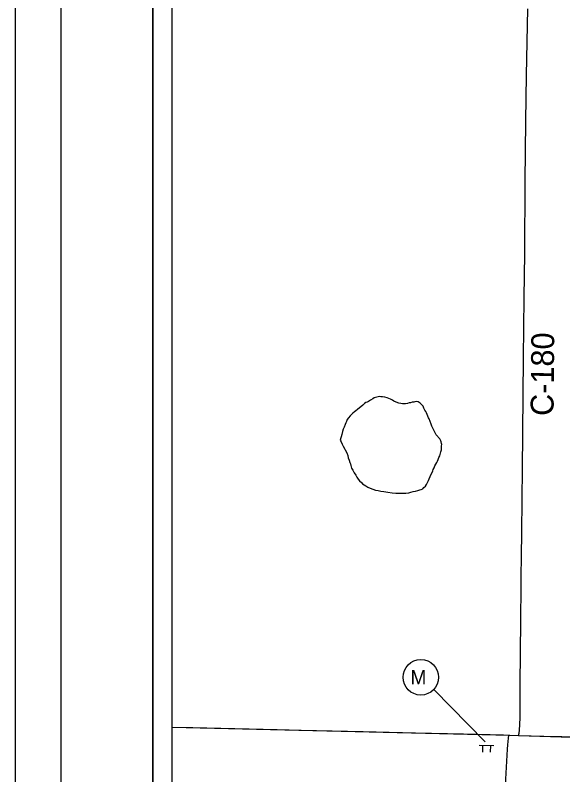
# Model space of a CAD drawing. Extents: x 1 to 1971, y -2 to 1107.
# Drawn here: x 1651.46 to 1657.44, y 1091.98 to 1100.26 of the extents above; entities that cross this region are included whole.
import ezdxf

# ---------------------------------------------------------------- set-up
doc = ezdxf.new("R2010")
doc.units = 0
for name, color, linetype in [('GM_X_County_Road', 7, 'Continuous'), ('GM_X_County_Road_Text', 7, 'Continuous'), ('GM_X_Minor_River', 7, 'Continuous'), ('GM_X_Township', 7, 'Continuous'), ('GM_X_Township_Road', 7, 'Continuous'), ('SH_Border', 7, 'Continuous'), ('SH_Cut_Line', 7, 'Continuous'), ('SH_Data', 7, 'Continuous'), ('SH_Text', 7, 'Continuous'), ('SN_P_Signs', 7, 'Continuous')]:
    doc.layers.add(name, color=color, linetype=linetype)

msp = doc.modelspace()

# ---------------------------------------------------------------- linework, layer by layer
at = {"layer": 'GM_X_County_Road'}
for points in [[(1656.9539, 1092.4077), (1656.9591, 1092.4332), (1656.9636, 1092.4628), (1656.965, 1092.4774), (1656.9669, 1092.5129), (1656.97, 1092.6154), (1656.9719, 1092.9605), (1656.9793, 1093.661), (1656.9822, 1094.0329), (1656.9825, 1094.1201), (1656.9871, 1094.3825), (1656.9878, 1094.6012), (1656.9921, 1094.995), (1656.9954, 1095.3015), (1657.0088, 1096.5272), (1657.0119, 1096.8554), (1657.0164, 1097.1823), (1657.0216, 1097.6632), (1657.0277, 1098.4513), (1657.0348, 1099.1076), (1657.0408, 1099.6108), (1657.0533, 1100.333)], [(1656.9539, 1092.4077), (1656.9591, 1092.4332), (1656.9636, 1092.4628), (1656.965, 1092.4774), (1656.9669, 1092.5129), (1656.97, 1092.6154), (1656.9719, 1092.9605), (1656.9793, 1093.661), (1656.9822, 1094.0329), (1656.9825, 1094.1201), (1656.9871, 1094.3825), (1656.9878, 1094.6012), (1656.9921, 1094.995), (1656.9954, 1095.3015), (1657.0088, 1096.5272), (1657.0119, 1096.8554), (1657.0164, 1097.1823), (1657.0216, 1097.6632), (1657.0277, 1098.4513), (1657.0348, 1099.1076), (1657.0408, 1099.6108), (1657.0533, 1100.333)], [(1656.6538, 1088.9713), (1656.6824, 1089.549), (1656.7502, 1090.7723), (1656.779, 1091.2527), (1656.8004, 1091.6678), (1656.8346, 1092.2577), (1656.8383, 1092.3049), (1656.8451, 1092.3768), (1656.8483, 1092.4109)], [(1656.6538, 1088.9713), (1656.6824, 1089.549), (1656.7502, 1090.7723), (1656.779, 1091.2527), (1656.8004, 1091.6678), (1656.8346, 1092.2577), (1656.8383, 1092.3049), (1656.8451, 1092.3768), (1656.8483, 1092.4109)], [(1656.8483, 1092.4109), (1656.9539, 1092.4077)], [(1656.8483, 1092.4109), (1656.9539, 1092.4077)]]:
    msp.add_lwpolyline(points, dxfattribs=at)
at = {"layer": 'GM_X_Minor_River'}
for points in [[(1656.055, 1095.6861), (1656.0243, 1095.7442), (1656.0138, 1095.7658), (1656.0086, 1095.7792), (1656.0008, 1095.8034), (1655.9774, 1095.86), (1655.9722, 1095.8735), (1655.9643, 1095.8896), (1655.9565, 1095.9085), (1655.9486, 1095.9247), (1655.9408, 1095.9408), (1655.9329, 1095.957), (1655.9224, 1095.9759), (1655.912, 1095.9975), (1655.8934, 1096.0165), (1655.8802, 1096.0327), (1655.8589, 1096.0464), (1655.8401, 1096.0493), (1655.824, 1096.0468), (1655.8105, 1096.0443), (1655.7944, 1096.0419), (1655.7755, 1096.0367), (1655.7593, 1096.0343), (1655.7432, 1096.0291), (1655.7216, 1096.0241), (1655.7001, 1096.0243), (1655.6867, 1096.0245), (1655.668, 1096.0274), (1655.6465, 1096.0331), (1655.6198, 1096.0415), (1655.5931, 1096.0552), (1655.5798, 1096.0634), (1655.5558, 1096.0771), (1655.5397, 1096.0827), (1655.5211, 1096.091), (1655.4943, 1096.0967), (1655.4701, 1096.0997), (1655.4514, 1096.1026), (1655.4379, 1096.1028), (1655.3922, 1096.0953), (1655.3787, 1096.0902), (1655.3625, 1096.0797), (1655.3381, 1096.0639), (1655.3164, 1096.0508), (1655.3029, 1096.0429), (1655.2894, 1096.0377), (1655.2732, 1096.0272), (1655.2569, 1096.0114), (1655.2324, 1095.9903), (1655.2189, 1095.9797), (1655.1972, 1095.964), (1655.1782, 1095.9481), (1655.1646, 1095.9376), (1655.1456, 1095.9218), (1655.1266, 1095.9059), (1655.1157, 1095.8927), (1655.0993, 1095.8715), (1655.0857, 1095.8529), (1655.0774, 1095.8316), (1655.0691, 1095.8156), (1655.0635, 1095.7996), (1655.0524, 1095.7703), (1655.0414, 1095.749), (1655.033, 1095.7224), (1655.0255, 1095.6907)], [(1655.0255, 1095.6907), (1655.0073, 1095.6283), (1655.018, 1095.6095), (1655.0286, 1095.5854), (1655.042, 1095.564), (1655.0819, 1095.489), (1655.0899, 1095.4622), (1655.0952, 1095.4354), (1655.1058, 1095.4086), (1655.1138, 1095.3845), (1655.1191, 1095.3711), (1655.1244, 1095.3524), (1655.1324, 1095.3229), (1655.1457, 1095.3015), (1655.1617, 1095.272), (1655.1777, 1095.2452), (1655.191, 1095.2237), (1655.2044, 1095.2023), (1655.2177, 1095.1862), (1655.2391, 1095.1647), (1655.2524, 1095.1513), (1655.2711, 1095.1405), (1655.2871, 1095.1298), (1655.3112, 1095.1163), (1655.3353, 1095.1029), (1655.3647, 1095.0921), (1655.3941, 1095.084), (1655.4208, 1095.0785), (1655.4502, 1095.0731), (1655.485, 1095.0676), (1655.5278, 1095.0595), (1655.5759, 1095.054), (1655.6134, 1095.0512), (1655.6455, 1095.0484), (1655.6696, 1095.0483), (1655.7017, 1095.0509), (1655.7258, 1095.0508), (1655.7552, 1095.0534), (1655.7793, 1095.0613), (1655.8034, 1095.0666), (1655.8302, 1095.0719), (1655.8543, 1095.0798), (1655.8757, 1095.0851), (1655.8918, 1095.0904), (1655.9079, 1095.0984), (1655.9213, 1095.1117), (1655.94, 1095.1277), (1655.9508, 1095.1437), (1655.9615, 1095.1678), (1655.9723, 1095.1865), (1655.9803, 1095.2052), (1655.9884, 1095.2319), (1656.018, 1095.2933), (1656.0234, 1095.3067), (1656.0341, 1095.3254), (1656.0422, 1095.3495), (1656.053, 1095.3655), (1656.061, 1095.3842), (1656.0691, 1095.4002), (1656.0772, 1095.4189), (1656.0852, 1095.4376), (1656.0933, 1095.4563), (1656.0987, 1095.4723), (1656.1041, 1095.4857), (1656.1068, 1095.5017), (1656.1122, 1095.5231), (1656.1149, 1095.5445), (1656.115, 1095.5659), (1656.1177, 1095.5793), (1656.115, 1095.5927), (1656.1097, 1095.6088), (1656.1071, 1095.6221), (1656.0937, 1095.6409), (1656.055, 1095.6861)]]:
    msp.add_lwpolyline(points, dxfattribs=at)
at = {"layer": 'GM_X_Township'}
msp.add_lwpolyline([(1653.1763, 1092.4976), (1656.8592, 1092.4086), (1656.9549, 1092.4071), (1660.4424, 1092.2976), (1663.9517, 1092.2334), (1668.658, 1092.1116), (1671.0761, 1092.0354), (1672.2022, 1091.993)], dxfattribs=at)
at = {"layer": 'GM_X_Township_Road'}
for points in [[(1653.1763, 1092.4975), (1653.4015, 1092.4929), (1654.3201, 1092.4717), (1654.5825, 1092.4645), (1655.2605, 1092.4486), (1655.8291, 1092.4348), (1656.3539, 1092.4224), (1656.7913, 1092.4126), (1656.8483, 1092.4109)], [(1653.1763, 1092.4975), (1653.4015, 1092.4929), (1654.3201, 1092.4717), (1654.5825, 1092.4645), (1655.2605, 1092.4486), (1655.8291, 1092.4348), (1656.3539, 1092.4224), (1656.7913, 1092.4126), (1656.8483, 1092.4109)], [(1656.9539, 1092.4077), (1657.2287, 1092.3994), (1657.8192, 1092.386), (1659.35, 1092.3476), (1659.8311, 1092.3358), (1660.3997, 1092.32), (1660.4916, 1092.3184)], [(1656.9539, 1092.4077), (1657.2287, 1092.3994), (1657.8192, 1092.386), (1659.35, 1092.3476), (1659.8311, 1092.3358), (1660.3997, 1092.32), (1660.4916, 1092.3184)]]:
    msp.add_lwpolyline(points, dxfattribs=at)
at = {"layer": 'SH_Border'}
for points in [[(1651.9632, 1106.1005), (1652.9632, 1106.1005), (1652.9632, 1085.1005), (1651.9632, 1085.1005)], [(1652.9632, 1106.1005), (1684.9632, 1106.1005), (1684.9632, 1085.1005), (1652.9632, 1085.1005)]]:
    msp.add_lwpolyline(points, close=True, dxfattribs=at)
at = {"layer": 'SH_Cut_Line'}
msp.add_lwpolyline([(1651.4632, 1084.6005), (1685.4632, 1084.6005), (1685.4632, 1106.6005), (1651.4632, 1106.6005)], close=True, dxfattribs=at)
at = {"layer": 'SH_Data'}
msp.add_lwpolyline([(1653.1763, 1105.4005), (1672.2022, 1105.4005), (1672.2022, 1085.8005), (1653.1763, 1085.8005)], close=True, dxfattribs=at)
at = {"layer": 'SH_Text'}
msp.add_line((1656.5913, 1092.3368), (1656.0306, 1092.9094), dxfattribs=at)
msp.add_circle((1655.8884, 1093.0408), 0.1936, dxfattribs=at)
at = {"layer": 'SN_P_Signs'}
for p, q in [((1656.5251, 1092.3023), (1656.6848, 1092.2971)), ((1656.562, 1092.3011), (1656.5596, 1092.2258)), ((1656.6463, 1092.2984), (1656.6439, 1092.2231))]:
    msp.add_line(p, q, dxfattribs=at)

# ---------------------------------------------------------------- texts
at = {"layer": 'GM_X_County_Road_Text'}
msp.add_text('C-180', height=0.25, rotation=89.44765, dxfattribs=at).set_placement((1657.335, 1095.8916))
at = {"layer": 'SH_Text'}
msp.add_text('M', height=0.156, dxfattribs=at).set_placement((1655.7745, 1092.9628))

doc.saveas('drawing.dxf')
